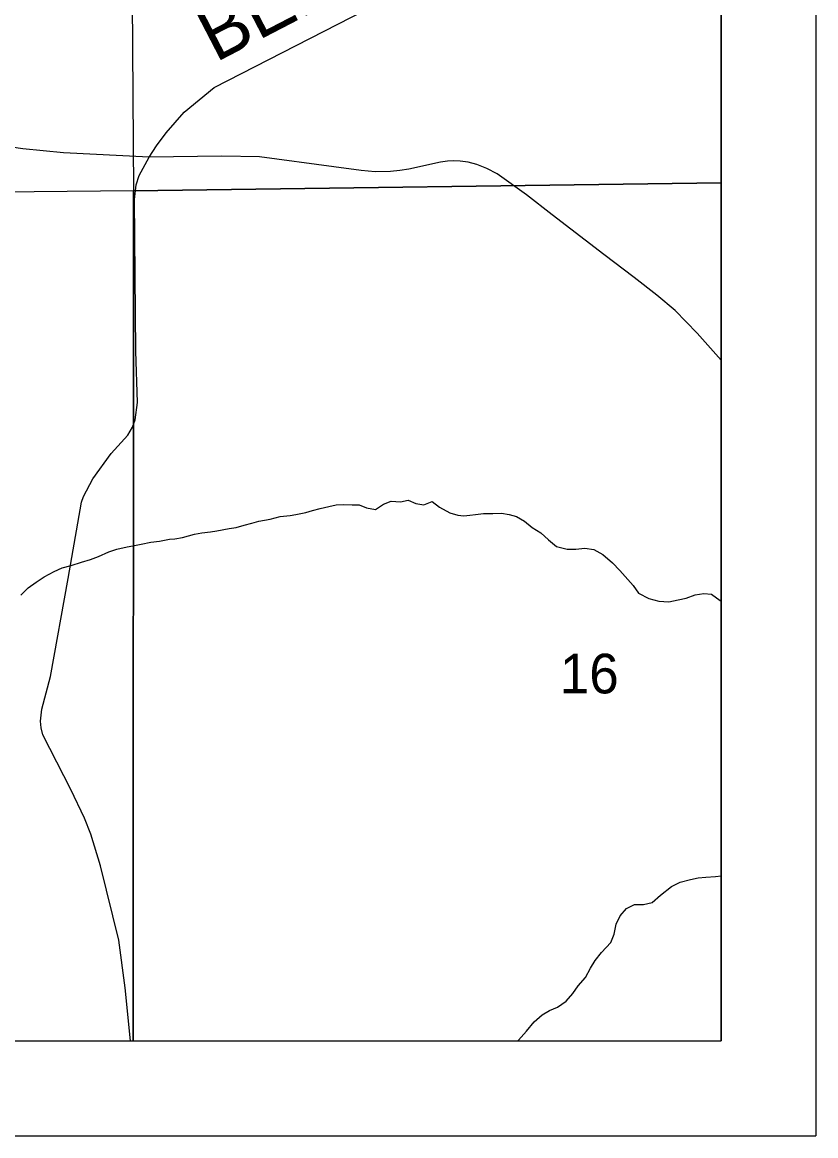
# Model space of a CAD drawing. Extents: x 0 to 34, y 0 to 22.
# Drawn here: x 8.162 to 9, y 14 to 15.175 of the extents above; entities that cross this region are included whole.
import ezdxf

# ---------------------------------------------------------------- set-up
doc = ezdxf.new("R2010")
doc.units = 0
for name, color, linetype in [('Default', 7, 'Continuous'), ('SH_Cut_Line', 7, 'Continuous'), ('SH_Data', 7, 'Continuous')]:
    doc.layers.add(name, color=color, linetype=linetype)

msp = doc.modelspace()

# ---------------------------------------------------------------- linework, layer by layer
at = {"layer": 'Default'}
for points in [[(6.2892, 14.1), (8.9, 14.1), (8.9, 17.02), (8.2009, 17.0196), (7.211, 17.0191), (7.2045, 17.0191), (6.9328, 17.0189), (6.927, 17.0189), (6.6903, 17.0144), (6.3876, 17.0173), (6.3215, 17.0189), (6.2871, 17.0188), (6.2922, 16.0152), (6.2959, 15.2705), (6.2926, 14.8972), (6.2889, 14.4906), (6.2892, 14.18)], [(8.9, 15.006), (8.9, 16.013), (8.2726, 16.0048), (8.2795, 14.9973)], [(8.2726, 16.0048), (8.2795, 14.9973), (7.2656, 14.9873), (7.265, 16.0012)], [(8.2792, 14.1), (8.9, 14.1), (8.9, 15.006), (8.2795, 14.9973)], [(7.2754, 14.1), (8.2792, 14.1), (8.2795, 14.9973), (7.2656, 14.9873)]]:
    msp.add_lwpolyline(points, close=True, dxfattribs=at)
for points in [[(8.2961, 15.0329), (8.3038, 15.0449), (8.3142, 15.0588), (8.333, 15.0804), (8.3646, 15.1066), (8.5675, 15.2107), (8.5826, 15.2226), (8.5909, 15.2326), (8.6017, 15.2586), (8.6251, 15.3794), (8.6275, 15.4004), (8.6333, 15.4648), (8.6338, 15.5043)], [(8.2961, 15.0329), (8.2057, 15.0376), (8.1628, 15.0417), (8.1384, 15.0454)], [(8.2764, 14.1), (8.2709, 14.1561), (8.2639, 14.2066), (8.2448, 14.2848), (8.2345, 14.3182), (8.2279, 14.3353), (8.2134, 14.3656), (8.1839, 14.4231), (8.1819, 14.4304), (8.1814, 14.4376), (8.1828, 14.4502), (8.192, 14.4849), (8.2107, 14.5882), (8.2246, 14.6687), (8.2269, 14.6749), (8.2365, 14.6935), (8.2561, 14.72), (8.2734, 14.7396), (8.2786, 14.7479), (8.2812, 14.7556), (8.2837, 14.7739), (8.2819, 14.8283), (8.2806, 14.9884), (8.2822, 15.0036), (8.2855, 15.0137), (8.2961, 15.0329)], [(8.9, 14.8187), (8.8749, 14.8473), (8.8515, 14.8711), (8.8322, 14.8872), (8.8084, 14.906), (8.7763, 14.9301), (8.7216, 14.972), (8.6945, 14.9933), (8.6637, 15.0152), (8.6527, 15.0209), (8.6422, 15.0251), (8.633, 15.0276), (8.6244, 15.0288), (8.6178, 15.0292), (8.6112, 15.0289), (8.6038, 15.0278), (8.5702, 15.0202), (8.5607, 15.0189), (8.5509, 15.018), (8.5349, 15.0175), (8.52, 15.0188), (8.491, 15.0229), (8.4126, 15.0334), (8.373, 15.0341), (8.2961, 15.0329)], [(8.1605, 14.5705), (8.1684, 14.5783), (8.1766, 14.5845), (8.1853, 14.5899), (8.1958, 14.5957), (8.2041, 14.5993), (8.2136, 14.6021), (8.2246, 14.6053), (8.234, 14.6084), (8.2427, 14.6116), (8.2536, 14.6163), (8.262, 14.6191), (8.2729, 14.6215), (8.279, 14.6228), (8.2877, 14.6244), (8.2979, 14.6264), (8.307, 14.6277), (8.3176, 14.6298), (8.3233, 14.6302), (8.3313, 14.6315), (8.3438, 14.6351), (8.3517, 14.6363), (8.3608, 14.6376), (8.3676, 14.6385), (8.3805, 14.6409), (8.3881, 14.6422), (8.3964, 14.6446), (8.4044, 14.6466), (8.4119, 14.6486), (8.4237, 14.651), (8.4343, 14.6535), (8.4449, 14.6547), (8.4509, 14.6556), (8.4615, 14.658), (8.4687, 14.66), (8.4767, 14.662), (8.4858, 14.6641), (8.4937, 14.6661), (8.5017, 14.6662), (8.5104, 14.6659), (8.518, 14.666), (8.5257, 14.6627), (8.5352, 14.661), (8.5434, 14.6668), (8.5518, 14.6699), (8.5616, 14.6693), (8.5696, 14.671), (8.5776, 14.6673), (8.586, 14.6659), (8.5951, 14.6694), (8.6027, 14.6635), (8.6135, 14.6575), (8.6222, 14.655), (8.6283, 14.6543), (8.6348, 14.6552), (8.6408, 14.6556), (8.6492, 14.6569), (8.659, 14.6567), (8.6681, 14.6572), (8.6761, 14.6558), (8.6841, 14.6536), (8.6926, 14.6488), (8.7006, 14.6421), (8.7098, 14.6365), (8.7179, 14.629), (8.7264, 14.6219), (8.7374, 14.619), (8.7465, 14.6192), (8.756, 14.6201), (8.7655, 14.6187), (8.7751, 14.6135), (8.7855, 14.6049), (8.7932, 14.5967), (8.8071, 14.5809), (8.8129, 14.5726), (8.8236, 14.5671), (8.8343, 14.5642), (8.8449, 14.5636), (8.8548, 14.5656), (8.8631, 14.5673), (8.8726, 14.5708), (8.8817, 14.5725)], [(8.8817, 14.5725), (8.89, 14.5718), (8.8989, 14.5651), (8.9, 14.5646)], [(8.6854, 14.1), (8.686, 14.1009), (8.6946, 14.1105), (8.7025, 14.1201), (8.7111, 14.1275), (8.719, 14.1321), (8.7273, 14.1357), (8.7363, 14.1419), (8.7434, 14.1503), (8.749, 14.1584), (8.7569, 14.1672), (8.762, 14.1768), (8.7672, 14.1849), (8.7736, 14.1933), (8.7837, 14.2041), (8.7873, 14.2129), (8.7891, 14.2235), (8.7935, 14.232), (8.8002, 14.24), (8.8085, 14.244), (8.818, 14.2441), (8.8271, 14.2461), (8.8361, 14.2538), (8.8478, 14.2631), (8.8568, 14.2678), (8.8678, 14.2706), (8.8757, 14.2723), (8.8841, 14.2731), (8.8943, 14.2737), (8.9, 14.2745)]]:
    msp.add_lwpolyline(points, dxfattribs=at)
at = {"layer": 'SH_Cut_Line'}
msp.add_lwpolyline([(2.1, 17.0156), (2.1, 14.1), (8.9, 14.1), (8.9, 17.02)], dxfattribs=at)
at = {"layer": 'SH_Data'}
for p, q in [((9, 21), (9, 14)), ((8.9, 20.9), (8.9, 14.1)), ((2.1, 14.1), (8.9, 14.1)), ((2, 14), (9, 14))]:
    msp.add_line(p, q, dxfattribs=at)

# ---------------------------------------------------------------- texts
at = {"layer": 'Default'}
for s, height, rotation, p in [('BELL', 0.05682, 27.4256, (8.3661, 15.1325)), ('16', 0.04186, 0, (8.7297, 14.4669))]:
    msp.add_text(s, height=height, rotation=rotation, dxfattribs=at).set_placement(p)

doc.saveas('drawing.dxf')
